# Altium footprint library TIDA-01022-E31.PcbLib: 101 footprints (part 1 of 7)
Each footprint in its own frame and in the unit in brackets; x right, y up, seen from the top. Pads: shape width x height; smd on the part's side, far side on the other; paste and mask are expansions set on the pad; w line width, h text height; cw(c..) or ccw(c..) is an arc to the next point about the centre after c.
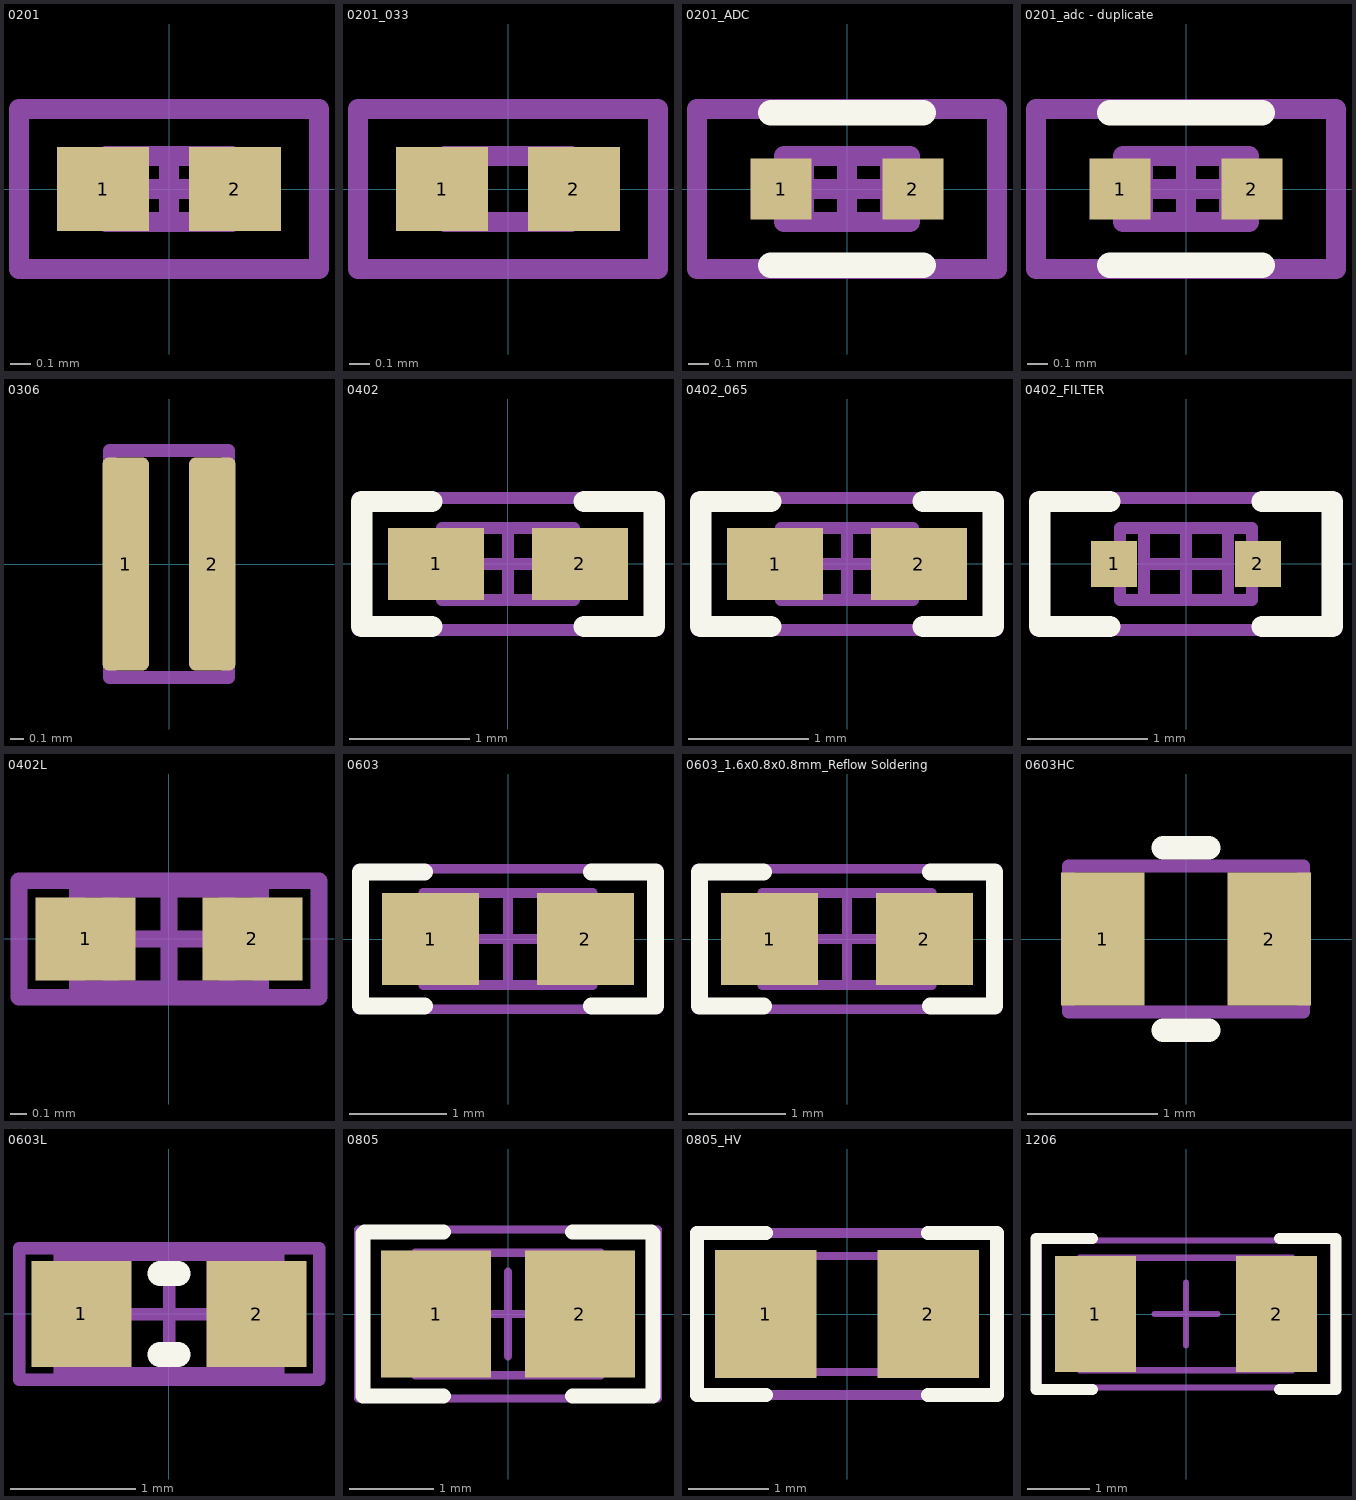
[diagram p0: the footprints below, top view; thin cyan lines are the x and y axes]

## 0201 [mm] "Data from Kemet datasheet CC101_COM dated 7/28/11"
height 0.26
pads (2):
  rect 0.46x0.42 smd mask+0.048: 1(-0.33,0) 2(0.33,0)
Mechanical 5:
  lines w0.1: -0.75,-0.4 -0.75,0.4 0.75,0.4 0.75,-0.4 -0.75,-0.4
  text ".Designator" at 1.483,7.033 h0.51
Mechanical 13:
  lines w0.1: -0.215,-0.165 -0.215,0.165 ; 0.215,-0.165 0.215,0.165 ; -0.315,-0.165 0.315,-0.165 0.315,0.165 -0.315,0.165 -0.315,-0.165
Mechanical 15:
  lines w0.1: -0.165,0 0.165,0 ; 0,-0.165 0,0.165 ; -0.75,-0.4 0.75,-0.4 0.75,0.4 -0.75,0.4 -0.75,-0.4
3D body: height 0.26, standoff 0, extent 0.216,-0.164 0.314,0.164
3D body: height 0.26, standoff 0, extent -0.214,-0.164 0.214,0.164
3D body: height 0.26, standoff 0, extent -0.314,-0.164 -0.216,0.164

## 0201_033 [mm] "SMD, 2-Leads, Height 0.33mm"
height 0.33
pads (2):
  rect 0.46x0.42 smd mask+0.048: 1(-0.33,0) 2(0.33,0)
Mechanical 5:
  lines w0.1: -0.75,-0.4 0.75,-0.4 0.75,0.4 -0.75,0.4 -0.75,-0.4
  text ".Designator" at -0.97,0.647 h0.51
Mechanical 13:
  lines w0.1: -0.215,-0.165 -0.215,0.165 ; 0.215,-0.165 0.215,0.165 ; -0.315,-0.165 -0.315,0.165 0.315,0.165 0.315,-0.165 -0.315,-0.165
3D body: height 0.33, standoff 0, extent -0.314,-0.164 -0.216,0.164
3D body: height 0.33, standoff 0, extent -0.214,-0.164 0.214,0.164
3D body: height 0.33, standoff 0, extent 0.216,-0.164 0.314,0.164

## 0201_ADC [mil] "Data from Kemet datasheet CC101_COM dated 7/28/11"
height 10.24
pads (2):
  rect 12x12 smd mask+1.9: 1(-12.99,0) 2(12.99,0)
Top Overlay:
  lines w5: -15,-15 15,-15 ; -15,15 15,15
Mechanical 5:
  lines w3.94: -29.53,-15.75 29.53,-15.75 29.53,15.75 -29.53,15.75 -29.53,-15.75
  text ".Designator" at -25.46,-46.67 h20
Mechanical 13:
  lines w3.94: -8.46,-6.5 -8.46,6.5 ; 8.46,-6.5 8.46,6.5 ; -12.4,-6.5 -12.4,6.5 12.4,6.5 12.4,-6.5 -12.4,-6.5
Mechanical 15:
  lines w3.94: -6.5,0 6.5,0 ; 0,-6.5 0,6.5 ; -29.53,-15.75 -29.53,15.75 29.53,15.75 29.53,-15.75 -29.53,-15.75
3D body: height 10.24, standoff 0, extent -12.38,-6.48 -8.48,6.48
3D body: height 10.24, standoff 0, extent -8.44,-6.48 8.44,6.48
3D body: height 10.24, standoff 0, extent 8.48,-6.48 12.38,6.48

## 0201_adc - duplicate [mil]
pads (2):
  rect 12x12 smd mask+1.9: 1(-12.99,0) 2(12.99,0)
Top Overlay:
  lines w5: -15,-15 15,-15 ; -15,15 15,15
Mechanical 5:
  lines w3.94: -29.53,-15.75 -29.53,15.75 29.53,15.75 29.53,-15.75 -29.53,-15.75
  text ".Designator" at 36.66,-11.05 h20
Mechanical 13:
  lines w3.94: -8.46,-6.5 -8.46,6.5 ; 8.46,-6.5 8.46,6.5 ; -12.4,-6.5 12.4,-6.5 12.4,6.5 -12.4,6.5 -12.4,-6.5
Mechanical 15:
  lines w3.94: -6.5,0 6.5,0 ; 0,-6.5 0,6.5 ; -29.53,-15.75 29.53,-15.75 29.53,15.75 -29.53,15.75 -29.53,-15.75
3D body: height 10.24, standoff 0, extent 8.48,-6.48 12.38,6.48
3D body: height 10.24, standoff 0, extent -8.44,-6.48 8.44,6.48
3D body: height 10.24, standoff 0, extent -12.38,-6.48 -8.48,6.48

## 0306 [mm] "based on TDK recommendation (similar to Taiyo Yuden and MuRata)"
height 0.6
pads (2):
  rrect29% 0.35x1.6 smd: 1(-0.325,0) 2(0.325,0)
Mechanical 5:
  lines w0.1: -0.241,-0.851 -0.445,-0.851 ; -0.241,0.851 -0.445,0.851 ; 0.241,-0.851 0.445,-0.851 ; 0.241,0.851 0.445,0.851 ; -0.445,-0.851 -0.445,0.851 ; -0.445,-0.851 0.445,-0.851 ; -0.445,-0.851 -0.445,0.851 ; -0.445,0.851 0.445,0.851 ; 0.445,-0.851 0.445,0.851 ; 0.445,-0.851 0.445,0.851
  text ".Designator" at 0.306,-0.501 h0.51
3D body: height 0.6, standoff 0, extent 0.242,-0.85 0.444,0.85
3D body: height 0.6, standoff 0, extent -0.241,-0.85 0.241,0.85
3D body: height 0.6, standoff 0, extent -0.444,-0.85 -0.242,0.85

## 0402 [mm] "0402 from SM-752 data"
height 0.6
pads (2):
  rect 0.8x0.6 smd: 1(-0.6,0) 2(0.6,0)
Top Overlay:
  lines w0.178: -0.635,-0.521 -1.219,-0.521 -1.219,0.521 -0.635,0.521 ; 0.635,-0.521 1.219,-0.521 1.219,0.521 0.635,0.521
Mechanical 5:
  lines w0.1: -1.25,-0.55 -1.25,0.55 1.25,0.55 1.25,-0.55 -1.25,-0.55
  text ".Designator" at -0.964,-0.207 h0.51
Mechanical 13:
  lines w0.1: -0.35,-0.3 -0.35,0.3 ; 0.35,-0.3 0.35,0.3 ; -0.55,-0.3 0.55,-0.3 0.55,0.3 -0.55,0.3 -0.55,-0.3
Mechanical 15:
  lines w0.1: -0.3,0 0.3,0 ; 0,-0.3 0,0.3 ; -1.25,-0.55 1.25,-0.55 1.25,0.55 -1.25,0.55 -1.25,-0.55
3D body: height 0.6, standoff 0, extent 0.351,-0.299 0.549,0.299
3D body: height 0.6, standoff 0, extent -0.349,-0.299 0.349,0.299
3D body: height 0.6, standoff 0, extent -0.549,-0.299 -0.351,0.299

## 0402_065 [mm] "0402"
height 0.65
pads (2):
  rect 0.8x0.6 smd: 1(-0.6,0) 2(0.6,0)
Top Overlay:
  lines w0.178: -0.635,-0.521 -1.219,-0.521 -1.219,0.521 -0.635,0.521 ; 0.635,-0.521 1.219,-0.521 1.219,0.521 0.635,0.521
Mechanical 5:
  lines w0.1: -1.25,-0.55 -1.25,0.55 1.25,0.55 1.25,-0.55 -1.25,-0.55
  text ".Designator" at -1.117,-0.305 h0.51
Mechanical 13:
  lines w0.1: -0.35,-0.3 -0.35,0.3 ; 0.35,-0.3 0.35,0.3 ; -0.55,-0.3 0.55,-0.3 0.55,0.3 -0.55,0.3 -0.55,-0.3
Mechanical 15:
  lines w0.1: -0.3,0 0.3,0 ; 0,-0.3 0,0.3 ; -1.25,-0.55 1.25,-0.55 1.25,0.55 -1.25,0.55 -1.25,-0.55
3D body: height 0.65, standoff 0, extent 0.351,-0.299 0.549,0.299
3D body: height 0.65, standoff 0, extent -0.349,-0.299 0.349,0.299
3D body: height 0.65, standoff 0, extent -0.549,-0.299 -0.351,0.299

## 0402_FILTER [mil]
height 23.62
pads (2):
  rect 15x15 smd: 1(-23.62,0) 2(23.62,0)
Top Overlay:
  lines w7: -25,-20.5 -48,-20.5 -48,20.5 -25,20.5 ; 25,-20.5 48,-20.5 48,20.5 25,20.5
Mechanical 5:
  lines w3.94: -49.21,-21.65 -49.21,21.65 49.21,21.65 49.21,-21.65 -49.21,-21.65
  text ".Designator" at -34,31.27 h20
Mechanical 13:
  lines w3.94: -13.78,-11.81 -13.78,11.81 ; 13.78,-11.81 13.78,11.81 ; -21.65,-11.81 21.65,-11.81 21.65,11.81 -21.65,11.81 -21.65,-11.81
Mechanical 15:
  lines w3.94: -11.81,0 11.81,0 ; 0,-11.81 0,11.81 ; -49.21,-21.65 49.21,-21.65 49.21,21.65 -49.21,21.65 -49.21,-21.65
3D body: height 23.62, standoff 0, extent 13.8,-11.79 21.63,11.79
3D body: height 23.62, standoff 0, extent -13.76,-11.79 13.76,11.79
3D body: height 23.62, standoff 0, extent -21.63,-11.79 -13.8,11.79

## 0402L [mm] "0402 from SM-752 data"
height 0.6
pads (2):
  rect 0.6x0.5 smd: 1(-0.5,0) 2(0.5,0)
Mechanical 5:
  lines w0.1: -0.9,-0.35 0.9,-0.35 0.9,0.35 -0.9,0.35 -0.9,-0.35
  text ".Designator" at -0.754,0.633 h0.51
Mechanical 13:
  lines w0.1: -0.35,-0.3 -0.35,0.3 ; 0.35,-0.3 0.35,0.3 ; -0.55,-0.3 -0.55,0.3 0.55,0.3 0.55,-0.3 -0.55,-0.3
Mechanical 15:
  lines w0.1: -0.3,0 0.3,0 ; 0,-0.3 0,0.3 ; -0.9,-0.35 -0.9,0.35 0.9,0.35 0.9,-0.35 -0.9,-0.35
3D body: height 0.6, standoff 0, extent -0.549,-0.299 -0.351,0.299
3D body: height 0.6, standoff 0, extent -0.349,-0.299 0.349,0.299
3D body: height 0.6, standoff 0, extent 0.351,-0.299 0.549,0.299

## 0603 [mm] "0603 from SM-752 data"
height 1
pads (2):
  rect 1x0.95 smd: 1(-0.8,0) 2(0.8,0)
Top Overlay:
  lines w0.178: -0.864,-0.691 -1.524,-0.691 -1.524,0.693 -0.864,0.693 ; 0.864,-0.691 1.524,-0.691 1.524,0.693 0.864,0.693
Mechanical 5:
  lines w0.1: -1.55,-0.725 1.55,-0.725 1.55,0.725 -1.55,0.725 -1.55,-0.725
  text ".Designator" at -1.113,-0.34 h0.64
Mechanical 13:
  lines w0.1: -0.55,-0.475 -0.55,0.475 ; 0.55,-0.475 0.55,0.475 ; -0.875,-0.475 -0.875,0.475 0.875,0.475 0.875,-0.475 -0.875,-0.475
Mechanical 15:
  lines w0.1: -0.475,0 0.475,0 ; 0,-0.475 0,0.475 ; -1.55,-0.725 -1.55,0.725 1.55,0.725 1.55,-0.725 -1.55,-0.725
3D body: height 1, standoff 0, extent 0.551,-0.474 0.874,0.474
3D body: height 1, standoff 0, extent -0.549,-0.474 0.549,0.474
3D body: height 1, standoff 0, extent -0.874,-0.474 -0.551,0.474

## 0603_1.6x0.8x0.8mm_Reflow Soldering [mm]
pads (2):
  rect 1x0.95 smd: 1(-0.8,0) 2(0.8,0)
Top Overlay:
  lines w0.178: -0.864,-0.691 -1.524,-0.691 -1.524,0.693 -0.864,0.693 ; 0.864,-0.691 1.524,-0.691 1.524,0.693 0.864,0.693
Mechanical 5:
  lines w0.1: -1.55,-0.725 -1.55,0.725 1.55,0.725 1.55,-0.725 -1.55,-0.725
  text ".Designator" at -1.397,-0.381 h0.51
Mechanical 13:
  lines w0.1: -0.55,-0.475 -0.55,0.475 ; 0.55,-0.475 0.55,0.475 ; -0.875,-0.475 0.875,-0.475 0.875,0.475 -0.875,0.475 -0.875,-0.475
Mechanical 15:
  lines w0.1: -0.475,0 0.475,0 ; 0,-0.475 0,0.475 ; -1.55,-0.725 1.55,-0.725 1.55,0.725 -1.55,0.725 -1.55,-0.725
3D body: height 1, standoff 0, extent -0.874,-0.474 -0.551,0.474
3D body: height 1, standoff 0, extent -0.549,-0.474 0.549,0.474
3D body: height 1, standoff 0, extent 0.551,-0.474 0.874,0.474

## 0603HC [mm] "SMD, 2-Leads, Body 1.8x1.12mm, Lead Spacing 1.28mm"
height 1.02
pads (2):
  rect 0.64x1.02 smd: 1(-0.64,0) 2(0.64,0)
Top Overlay:
  lines w0.18: -0.175,-0.7 0.175,-0.7 ; -0.175,0.7 0.175,0.7
Mechanical 5:
  lines w0.1: -0.9,-0.56 -0.9,0.56 0.9,0.56 0.9,-0.56 -0.9,-0.56
  text ".Designator" at -0.568,-0.214 h0.51
3D body "Coilcraft-0603HC.stp": height 1.01, standoff -0.02, extent -0.9,-0.561 0.904,0.561

## 0603L [mm] "0603 from SM-752 data"
height 1
pads (2):
  rect 0.8x0.85 smd: 1(-0.7,0) 2(0.7,0)
Top Overlay:
  lines w0.2: -0.071,-0.325 0.071,-0.325 ; -0.071,0.325 0.071,0.325
Mechanical 5:
  lines w0.1: -1.2,-0.525 -1.2,0.525 1.2,0.525 1.2,-0.525 -1.2,-0.525
  text ".Designator" at -0.923,-0.294 h0.51
Mechanical 13:
  lines w0.1: -0.55,-0.475 -0.55,0.475 ; 0.55,-0.475 0.55,0.475 ; -0.875,-0.475 -0.875,0.475 0.875,0.475 0.875,-0.475 -0.875,-0.475
Mechanical 15:
  lines w0.1: -0.475,0 0.475,0 ; 0,-0.475 0,0.475 ; -1.2,-0.525 1.2,-0.525 1.2,0.525 -1.2,0.525 -1.2,-0.525
3D body: height 1, standoff 0, extent 0.551,-0.474 0.874,0.474
3D body: height 1, standoff 0, extent -0.549,-0.474 0.549,0.474
3D body: height 1, standoff 0, extent -0.874,-0.474 -0.551,0.474

## 0805 [mm] "0805 from SM-752 data"
height 1.45
pads (2):
  rect 1.3x1.5 smd: 1(-0.85,0) 2(0.85,0)
Top Overlay:
  lines w0.178: -0.762,-0.968 -1.717,-0.968 -1.717,0.95 -1.699,0.968 -0.762,0.968 ; 0.762,-0.968 1.717,-0.968 1.717,0.95 1.699,0.968 0.762,0.968
Mechanical 5:
  lines w0.1: -1.775,-1 -1.775,1 1.775,1 1.775,-1 -1.775,-1
  text ".Designator" at 0.981,0.17 h0.51
Mechanical 13:
  lines w0.1: -0.65,-0.725 -0.65,0.725 ; 0.65,-0.725 0.65,0.725 ; -1.1,-0.725 -1.1,0.725 1.1,0.725 1.1,-0.725 -1.1,-0.725
Mechanical 15:
  lines w0.1: -0.5,0 0.5,0 ; 0,-0.5 0,0.5 ; -1.775,-1 -1.775,1 1.775,1 1.775,-1 -1.775,-1
3D body: height 1.45, standoff 0, extent 0.651,-0.724 1.099,0.724
3D body: height 1.45, standoff 0, extent -0.649,-0.724 0.649,0.724
3D body: height 1.45, standoff 0, extent -1.099,-0.724 -0.651,0.724

## 0805_HV [mil] "0805 with 30mil clearance between pads"
height 57.09
pads (2):
  rect 50x63 smd: 1(-40,0) 2(40,0)
Top Overlay:
  lines w7: -40,-40 -74,-40 -74,0 -74,40 -40,40 ; 40,-40 74,-40 74,0 74,40 40,40
Mechanical 5:
  lines w5: -74,-40 -74,40 74,40 74,-40 -74,-40
  text ".Designator" at 36.68,13.08 h20
Mechanical 13:
  lines w3.94: -25.59,-28.54 -25.59,28.54 ; 25.59,-28.54 25.59,28.54 ; -43.31,-28.54 -43.31,28.54 43.31,28.54 43.31,-28.54 -43.31,-28.54
3D body: height 57.09, standoff 0, extent 25.61,-28.52 43.29,28.52
3D body: height 57.09, standoff 0, extent -25.57,-28.52 25.57,28.52
3D body: height 57.09, standoff 0, extent -43.29,-28.52 -25.61,28.52

## 1206 [mm] "1206 from SM-752 data"
height 1.35
pads (2):
  rect 1.3x1.85 smd: 1(-1.45,0) 2(1.45,0)
Top Overlay:
  lines w0.178: -1.5,-1.21 -2.4,-1.21 -2.4,1.21 -1.5,1.21 ; 1.5,-1.21 2.4,-1.21 2.4,1.21 1.5,1.21
Mechanical 5:
  lines w0.1: -1.7,-0.9 1.7,-0.9 1.7,0.9 -1.7,0.9 -1.7,-0.9
  text ".Designator" at 0.927,0.237 h0.51
Mechanical 13:
  lines w0.1: -1.2,-0.9 -1.2,0.9 ; 1.2,-0.9 1.2,0.9 ; -1.7,-0.9 1.7,-0.9 1.7,0.9 -1.7,0.9 -1.7,-0.9
Mechanical 15:
  lines w0.1: -0.5,0 0.5,0 ; 0,-0.5 0,0.5 ; -2.35,-1.175 2.35,-1.175 2.35,1.175 -2.35,1.175 -2.35,-1.175
3D body: height 1.35, standoff 0, extent -1.699,-0.899 -1.201,0.899
3D body: height 1.35, standoff 0, extent -1.199,-0.899 1.199,0.899
3D body: height 1.35, standoff 0, extent 1.201,-0.899 1.699,0.899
